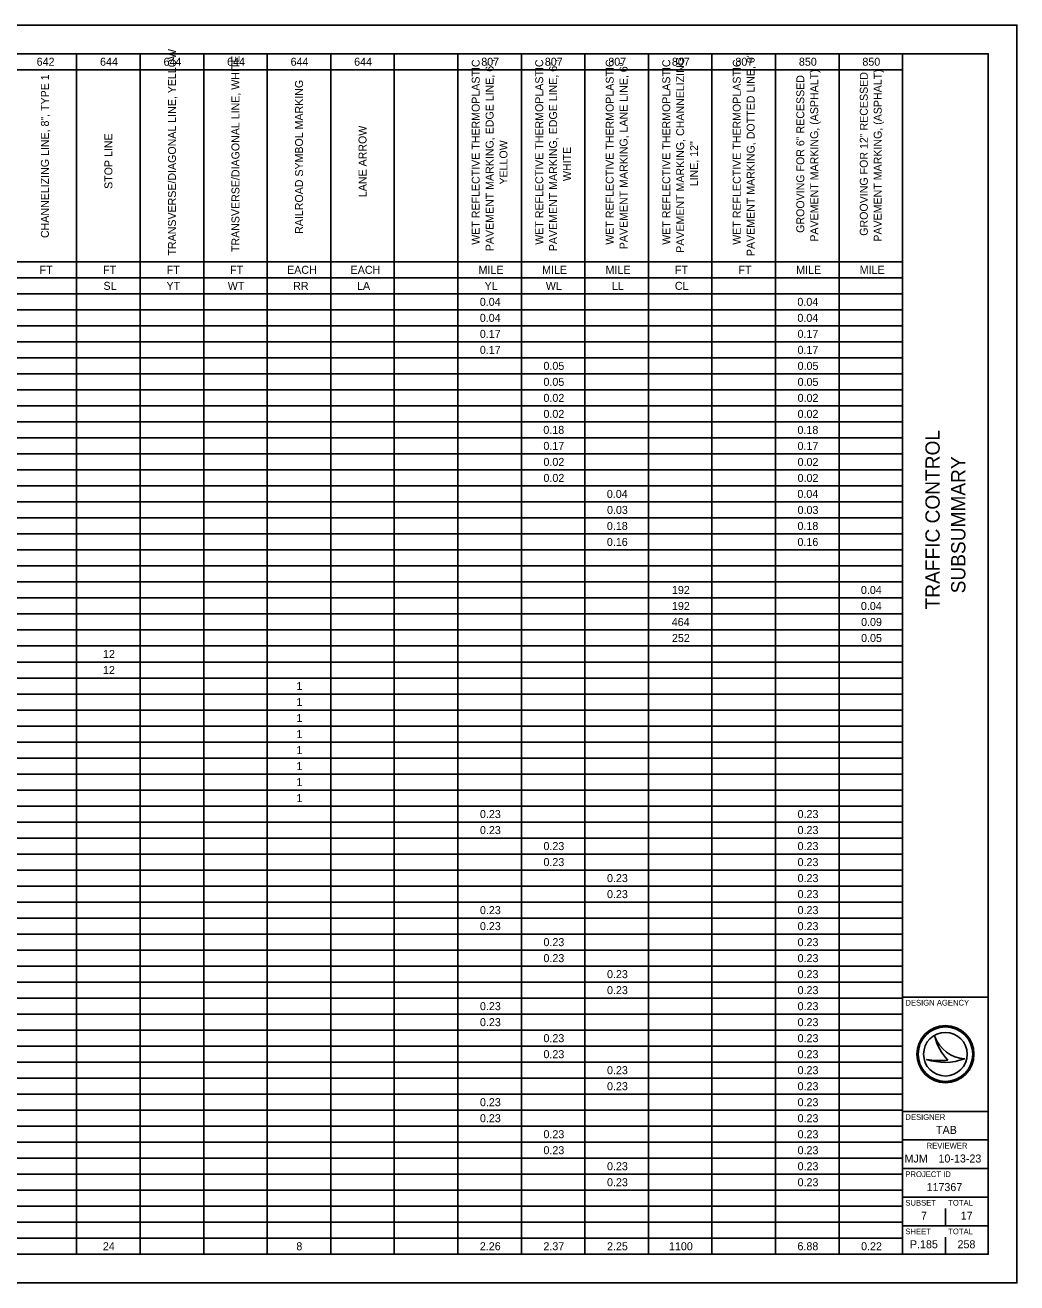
# Model space of a CAD drawing. Extents: x 0 to 34, y 0 to 22.
# Drawn here: x 16.65 to 34, y 0 to 22 of the extents above; entities that cross this region are included whole.
import ezdxf

# ---------------------------------------------------------------- set-up
doc = ezdxf.new("R2010")
doc.units = 0
for name, color, linetype in [('SH_Border', 7, 'Continuous'), ('SH_Cut_Line', 7, 'Continuous'), ('SH_Data', 7, 'Continuous'), ('SH_Text', 7, 'Continuous')]:
    doc.layers.add(name, color=color, linetype=linetype)

msp = doc.modelspace()

# ---------------------------------------------------------------- linework, layer by layer
at = {"layer": 'SH_Border'}
for p, q in [((32, 0.5), (32, 21.5)), ((32, 5), (33.5, 5)), ((32, 3), (33.5, 3)), ((32, 2.5), (33.5, 2.5)), ((32, 2), (33.5, 2)), ((32, 1.5), (33.5, 1.5)), ((32, 1), (33.5, 1))]:
    msp.add_line(p, q, dxfattribs=at)
msp.add_lwpolyline([(1.5, 21.5), (33.5, 21.5), (33.5, 0.5), (1.5, 0.5)], close=True, dxfattribs=at)
at = {"layer": 'SH_Cut_Line'}
msp.add_lwpolyline([(0, 0), (34, 0), (34, 22), (0, 22)], close=True, dxfattribs=at)
at = {"layer": 'SH_Data'}
for p, q in [((32.567, 4.31), (32.567, 4.31)), ((32.75, 4), (32.75, 4)), ((32.417, 3.91), (32.417, 3.91)), ((33.087, 3.919), (33.087, 3.919)), ((32.75, 1), (32.75, 1.3)), ((32.375, 0.675), (32.375, 0.675)), ((32.75, 0.5), (32.75, 0.8))]:
    msp.add_line(p, q, dxfattribs=at)
for radius in [0.5, 0.477, 0.477, 0.382]:
    msp.add_circle((32.75, 4), radius, dxfattribs=at)
for centre, radius, start, end in [((33.116, 4.498), 0.58, 198.9257, 198.9319), ((33.347, 4.47), 0.796, 191.6379, 191.6421), ((33.116, 4.498), 0.58, 198.9319, 267.1657), ((33.347, 4.47), 0.796, 191.6421, 226.0947), ((32.739, 4.87), 1.013, 251.4576, 290.0832), ((32.648, 5.154), 1.266, 259.4964, 259.4995), ((32.739, 4.87), 1.013, 251.4527, 251.4576), ((32.648, 5.154), 1.266, 259.4995, 276.6672)]:
    msp.add_arc(centre, radius, start, end, dxfattribs=at)
at = {"layer": 'SH_Text'}
for p, q in [((1.5, 21.5), (32, 21.5)), ((17.551, 21.5), (17.551, 0.5)), ((18.662, 21.5), (18.662, 0.5)), ((19.774, 21.5), (19.774, 0.5)), ((20.885, 21.5), (20.885, 0.5)), ((21.997, 21.5), (21.997, 0.5)), ((23.108, 21.5), (23.108, 0.5)), ((24.22, 21.5), (24.22, 0.5)), ((25.331, 21.5), (25.331, 0.5)), ((26.443, 21.5), (26.443, 0.5)), ((27.554, 21.5), (27.554, 0.5)), ((28.666, 21.5), (28.666, 0.5)), ((29.777, 21.5), (29.777, 0.5)), ((30.889, 21.5), (30.889, 0.5)), ((32, 21.5), (32, 0.5)), ((8.659, 21.22), (32, 21.22)), ((8.659, 17.86), (32, 17.86)), ((1.5, 17.58), (32, 17.58)), ((1.5, 17.3), (32, 17.3)), ((1.5, 17.02), (32, 17.02)), ((1.5, 16.74), (32, 16.74)), ((1.5, 16.46), (32, 16.46)), ((1.5, 16.18), (32, 16.18)), ((1.5, 15.9), (32, 15.9)), ((1.5, 15.62), (32, 15.62)), ((1.5, 15.34), (32, 15.34)), ((1.5, 15.06), (32, 15.06)), ((1.5, 14.78), (32, 14.78)), ((1.5, 14.5), (32, 14.5)), ((1.5, 14.22), (32, 14.22)), ((1.5, 13.94), (32, 13.94)), ((1.5, 13.66), (32, 13.66)), ((1.5, 13.38), (32, 13.38)), ((1.5, 13.1), (32, 13.1)), ((1.5, 12.82), (32, 12.82)), ((1.5, 12.54), (32, 12.54)), ((1.5, 12.26), (32, 12.26)), ((1.5, 11.98), (32, 11.98)), ((1.5, 11.7), (32, 11.7)), ((1.5, 11.42), (32, 11.42)), ((1.5, 11.14), (32, 11.14)), ((1.5, 10.86), (32, 10.86)), ((1.5, 10.58), (32, 10.58)), ((1.5, 10.3), (32, 10.3)), ((1.5, 10.02), (32, 10.02)), ((1.5, 9.74), (32, 9.74)), ((1.5, 9.46), (32, 9.46)), ((1.5, 9.18), (32, 9.18)), ((1.5, 8.9), (32, 8.9)), ((1.5, 8.62), (32, 8.62)), ((1.5, 8.34), (32, 8.34)), ((1.5, 8.06), (32, 8.06)), ((1.5, 7.78), (32, 7.78)), ((1.5, 7.5), (32, 7.5)), ((1.5, 7.22), (32, 7.22)), ((1.5, 6.94), (32, 6.94)), ((1.5, 6.66), (32, 6.66)), ((1.5, 6.38), (32, 6.38)), ((1.5, 6.1), (32, 6.1)), ((1.5, 5.82), (32, 5.82)), ((1.5, 5.54), (32, 5.54)), ((1.5, 5.26), (32, 5.26)), ((1.5, 4.98), (32, 4.98)), ((1.5, 4.7), (32, 4.7)), ((1.5, 4.42), (32, 4.42)), ((1.5, 4.14), (32, 4.14)), ((1.5, 3.86), (32, 3.86)), ((1.5, 3.58), (32, 3.58)), ((1.5, 3.3), (32, 3.3)), ((1.5, 3.02), (32, 3.02)), ((1.5, 2.74), (32, 2.74)), ((1.5, 2.46), (32, 2.46)), ((1.5, 2.18), (32, 2.18)), ((1.5, 1.9), (32, 1.9)), ((1.5, 1.62), (32, 1.62)), ((1.5, 1.34), (32, 1.34)), ((1.5, 1.06), (32, 1.06)), ((1.5, 0.78), (32, 0.78)), ((1.5, 0.5), (32, 0.5))]:
    msp.add_line(p, q, dxfattribs=at)

# ---------------------------------------------------------------- texts
at = {"layer": 'SH_Data'}
for s, p in [('TRAFFIC CONTROL', (32.65, 11.78)), ('SUBSUMMARY', (33.1, 12.061))]:
    msp.add_text(s, height=0.25, rotation=90, dxfattribs=at).set_placement(p)
for s, height, p in [('DESIGN AGENCY', 0.1, (32.05, 4.85)), ('DESIGNER', 0.1, (32.05, 2.85)), ('TAB', 0.14, (32.586, 2.605)), ('REVIEWER', 0.1, (32.422, 2.35)), ('MJM', 0.14, (32.035, 2.105)), ('10-13-23', 0.14, (32.629, 2.105)), ('PROJECT ID', 0.1, (32.05, 1.85)), ('117367', 0.14, (32.42, 1.605)), ('SUBSET', 0.1, (32.05, 1.35)), ('TOTAL', 0.1, (32.8, 1.35)), ('7', 0.14, (32.324, 1.105)), ('17', 0.14, (33.018, 1.105)), ('SHEET', 0.1, (32.05, 0.85)), ('TOTAL', 0.1, (32.8, 0.85)), ('P.185', 0.14, (32.129, 0.605)), ('258', 0.14, (32.962, 0.605))]:
    msp.add_text(s, height=height, dxfattribs=at).set_placement(p)
at = {"layer": 'SH_Text'}
for s, height, p in [('TRANSVERSE/DIAGONAL LINE, YELLOW', 0.13893, (19.288, 17.97)), ('TRANSVERSE/DIAGONAL LINE, WHITE', 0.13893, (20.399, 18.031)), ('WET REFLECTIVE THERMOPLASTIC ', 0.13893, (24.602, 18.159)), ('PAVEMENT MARKING, EDGE LINE, 6", ', 0.13893, (24.845, 18.046)), ('WET REFLECTIVE THERMOPLASTIC ', 0.13893, (25.713, 18.159)), ('PAVEMENT MARKING, EDGE LINE, 6", ', 0.13893, (25.956, 18.046)), ('WET REFLECTIVE THERMOPLASTIC ', 0.13893, (26.946, 18.159)), ('WET REFLECTIVE THERMOPLASTIC ', 0.13893, (27.936, 18.159)), ('PAVEMENT MARKING, CHANNELIZING ', 0.13893, (28.179, 18.017)), ('WET REFLECTIVE THERMOPLASTIC ', 0.13893, (29.169, 18.159)), ('PAVEMENT MARKING, DOTTED LINE, 6"', 0.13893, (29.412, 17.96)), ('CHANNELIZING LINE, 8", TYPE 1', 0.13893, (17.065, 18.276)), ('PAVEMENT MARKING, LANE LINE, 6"', 0.13893, (27.189, 18.08)), ('PAVEMENT MARKING, (ASPHALT)', 0.13893, (30.524, 18.213)), ('GROOVING FOR 12" RECESSED ', 0.13893, (31.392, 18.316)), ('PAVEMENT MARKING, (ASPHALT)', 0.13893, (31.635, 18.213)), ('RAILROAD SYMBOL MARKING', 0.13893, (21.511, 18.349)), ('GROOVING FOR 6" RECESSED ', 0.13893, (30.281, 18.367)), ('LANE ARROW', 0.1389, (22.622, 18.992)), ('STOP LINE', 0.1389, (18.176, 19.136)), ('YELLOW', 0.1389, (25.088, 19.212)), ('WHITE', 0.1389, (26.2, 19.273)), ('LINE, 12"', 0.1389, (28.422, 19.181))]:
    msp.add_text(s, height=height, rotation=90, dxfattribs=at).set_placement(p)
for s, p in [('642', (16.851, 21.29)), ('644', (17.96, 21.29)), ('644', (19.071, 21.29)), ('644', (20.183, 21.29)), ('644', (21.294, 21.29)), ('644', (22.406, 21.29)), ('807', (24.63, 21.29)), ('807', (25.742, 21.29)), ('807', (26.853, 21.29)), ('807', (27.965, 21.29)), ('807', (29.076, 21.29)), ('850', (30.187, 21.29)), ('850', (31.298, 21.29)), ('FT', (16.903, 17.65)), ('FT', (18.014, 17.65)), ('FT', (19.126, 17.65)), ('FT', (20.237, 17.65)), ('EACH', (21.232, 17.65)), ('EACH', (22.344, 17.65)), ('MILE', (24.582, 17.65)), ('MILE', (25.694, 17.65)), ('MILE', (26.805, 17.65)), ('FT', (28.017, 17.65)), ('FT', (29.129, 17.65)), ('MILE', (30.139, 17.65)), ('MILE', (31.251, 17.65)), ('SL', (18.021, 17.37)), ('YT', (19.123, 17.37)), ('WT', (20.195, 17.37)), ('RR', (21.338, 17.37)), ('LA', (22.456, 17.37)), ('YL', (24.687, 17.37)), ('WL', (25.759, 17.37)), ('LL', (26.916, 17.37)), ('CL', (28.017, 17.37)), ('0.04', (24.604, 17.09)), ('0.04', (30.161, 17.09)), ('0.04', (24.604, 16.81)), ('0.04', (30.161, 16.81)), ('0.17', (24.605, 16.53)), ('0.17', (30.163, 16.53)), ('0.17', (24.605, 16.25)), ('0.17', (30.163, 16.25)), ('0.05', (25.718, 15.97)), ('0.05', (30.164, 15.97)), ('0.05', (25.718, 15.69)), ('0.05', (30.164, 15.69)), ('0.02', (25.718, 15.41)), ('0.02', (30.164, 15.41)), ('0.02', (25.718, 15.13)), ('0.02', (30.164, 15.13)), ('0.18', (25.716, 14.85)), ('0.18', (30.162, 14.85)), ('0.17', (25.717, 14.57)), ('0.17', (30.163, 14.57)), ('0.02', (25.718, 14.29)), ('0.02', (30.164, 14.29)), ('0.02', (25.718, 14.01)), ('0.02', (30.164, 14.01)), ('0.04', (26.827, 13.73)), ('0.04', (30.161, 13.73)), ('0.03', (26.83, 13.45)), ('0.03', (30.164, 13.45)), ('0.18', (26.828, 13.17)), ('0.18', (30.162, 13.17)), ('0.16', (26.828, 12.89)), ('0.16', (30.162, 12.89)), ('192', (27.966, 12.05)), ('0.04', (31.272, 12.05)), ('192', (27.966, 11.77)), ('0.04', (31.272, 11.77)), ('464', (27.963, 11.49)), ('0.09', (31.275, 11.49)), ('252', (27.966, 11.21)), ('0.05', (31.275, 11.21)), ('12', (18.012, 10.93)), ('12', (18.012, 10.65)), ('1', (21.396, 10.37)), ('1', (21.396, 10.09)), ('1', (21.396, 9.81)), ('1', (21.396, 9.53)), ('1', (21.396, 9.25)), ('1', (21.396, 8.97)), ('1', (21.396, 8.69)), ('1', (21.396, 8.41)), ('0.23', (24.607, 8.13)), ('0.23', (30.164, 8.13)), ('0.23', (24.607, 7.85)), ('0.23', (30.164, 7.85)), ('0.23', (25.718, 7.57)), ('0.23', (30.164, 7.57)), ('0.23', (25.718, 7.29)), ('0.23', (30.164, 7.29)), ('0.23', (26.83, 7.01)), ('0.23', (30.164, 7.01)), ('0.23', (26.83, 6.73)), ('0.23', (30.164, 6.73)), ('0.23', (24.607, 6.45)), ('0.23', (30.164, 6.45)), ('0.23', (24.607, 6.17)), ('0.23', (30.164, 6.17)), ('0.23', (25.718, 5.89)), ('0.23', (30.164, 5.89)), ('0.23', (25.718, 5.61)), ('0.23', (30.164, 5.61)), ('0.23', (26.83, 5.33)), ('0.23', (30.164, 5.33)), ('0.23', (26.83, 5.05)), ('0.23', (30.164, 5.05)), ('0.23', (24.607, 4.77)), ('0.23', (30.164, 4.77)), ('0.23', (24.607, 4.49)), ('0.23', (30.164, 4.49)), ('0.23', (25.718, 4.21)), ('0.23', (30.164, 4.21)), ('0.23', (25.718, 3.93)), ('0.23', (30.164, 3.93)), ('0.23', (26.83, 3.65)), ('0.23', (30.164, 3.65)), ('0.23', (26.83, 3.37)), ('0.23', (30.164, 3.37)), ('0.23', (24.607, 3.09)), ('0.23', (30.164, 3.09)), ('0.23', (24.607, 2.81)), ('0.23', (30.164, 2.81)), ('0.23', (25.718, 2.53)), ('0.23', (30.164, 2.53)), ('0.23', (25.718, 2.25)), ('0.23', (30.164, 2.25)), ('0.23', (26.83, 1.97)), ('0.23', (30.164, 1.97)), ('0.23', (26.83, 1.69)), ('0.23', (30.164, 1.69)), ('24', (18.01, 0.57)), ('8', (21.395, 0.57)), ('2.26', (24.605, 0.57)), ('2.37', (25.717, 0.57)), ('2.25', (26.83, 0.57)), ('1100', (27.914, 0.57)), ('6.88', (30.162, 0.57)), ('0.22', (31.275, 0.57))]:
    msp.add_text(s, height=0.14, dxfattribs=at).set_placement(p)

doc.saveas('drawing.dxf')
